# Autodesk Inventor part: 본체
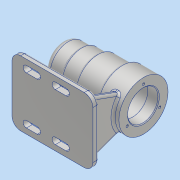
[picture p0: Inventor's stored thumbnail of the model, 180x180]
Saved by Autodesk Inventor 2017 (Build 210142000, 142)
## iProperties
Part Number: 본체
Material: 알루미늄 6061
Document SubType Name: Modeling
Designer: MRC
Density: 2.7 g/cm^3
Appearance: 알루미늄 - 평지
Author: MRC
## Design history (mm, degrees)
sketch "스케치2"
  geometry: L1 (56, 0)-(56, 34); L2 (56, 34)-(24, 34); L3 (24, 34)-(24, 30); L4 (24, 30)-(-10, 30); L5 (-10, 30)-(-10, 27); L6 (-10, 27)-(-32, 27); L7 (-32, 27)-(-32, 25); L8 (-32, 25)-(-56, 25); L9 (-56, 25)-(-56, 0); L10 (-56, 0)-(56, 0); 2 further points
  constraints: 20 end point, 8 perpendicular, 2 midpoint, 1 coincident, 1 horizontal, 1 vertical
  dimensions: "d0" = 68 diameter of L2 L10; "d1" = 60 diameter of L4 L10; "d2" = 54 diameter of L6 L10; "d3" = 50 diameter of L8 L10; "d4" = 24 distance of L7.end L8.end; "d5" = 46 distance from line of L5.end L9; "d6" = 80 distance from line of L3.end L9; "d7" = 112 distance between parallel lines of L1 L9
revolve "회전1" sketch "스케치2" stored, may be unused: angle "d8" = 90 deg
sketch "스케치3"
  geometry: L1 (56, -34)-(56, 34) reference; L2 (56, 21)-(41, 21); L3 (41, 21)-(41, 24); L4 (41, 24)-(-13, 24); L5 (-13, 24)-(-13, 21); L6 (-13, 21)-(-25, 21); L7 (-25, 21)-(-25, 17.5); L8 (-25, 17.5)-(-43, 17.5); L9 (-43, 17.5)-(-43, 16); L10 (-43, 16)-(-47, 16); L11 (-47, 16)-(-47, 10.5); L12 (-47, 10.5)-(-50, 10.5); L13 (-50, 10.5)-(-50, 0); L14 (-50, 0)-(56, 0); 1 further point
  constraints: 26 end point, 11 perpendicular, 1 horizontal, 1 midpoint, 1 point on line
  dimensions: "d9" = 21 diameter of L12 L14; "d10" = 15 distance of L2.start L2.end; "d11" = 54 distance of L3.end L4.end; "d12" = 12 distance of L5.end L6.end; "d13" = 18 distance of L7.end L8.end; "d14" = 3 distance of L11.end L12.end; "d15" = 4 distance of L9.end L10.end; "d16" = 42 diameter of L2 L14; "d17" = 48 diameter of L4 L14; "d18" = 32 diameter of L10 L14; "d19" = 35 diameter of L8 L14; "d20" = 42 diameter of L6 L14
revolve "회전2" sketch "스케치3" stored, may be unused: angle "d21" = 90 deg
fillet "모깎기1" dims "d22" = 3, "d23" = 0.3
chamfer "모따기1" distance "d24" = 1; stored, may be unused: second distance "d25" = 2, angle "d26" = 45 deg
sketch "스케치5"
  geometry: L1 (-56, -62)-(56, -62); L2 (56, -62)-(56, -70); L3 (56, -70)-(-56, -70); L4 (-56, -70)-(-56, -62); 2 further points
  constraints: 8 end point, 2 parallel, 1 horizontal, 1 midpoint, 1 perpendicular, 1 vertical alignment
  dimensions: "d27" = 8 distance of L1.end L2.end; "d28" = 70 distance from line of L3 point (0, 0); "d29" = 112 distance of L2.end L3.end
extrude "돌출1" join sketch "스케치5" stored distance "d30" = 90; taper "d31" = 0 deg
sketch "스케치6"
  geometry: L1 (0, 90)-(0, 0) reference; L2 (0, 90)-(112, 90) reference; L3 (20, 78)-(35, 78); L4 (20, 82.5)-(35, 82.5); L5 (35, 73.5)-(20, 73.5); L6 (60, 78)-(75, 78); L7 (60, 73.5)-(75, 73.5); L8 (75, 82.5)-(60, 82.5); A1 r 4.5 centre (20, 78) between (20, 82.5) and (20, 73.5); A2 r 4.5 centre (35, 78) between (35, 73.5) and (35, 82.5); A3 r 4.5 centre (60, 78) between (60, 82.5) and (60, 73.5); A4 r 4.5 centre (75, 78) between (75, 73.5) and (75, 82.5); 3 further points
  constraints: 16 end point, 8 point on circle, 8 tangent, 4 centre point, 3 parallel, 2 midpoint, 2 point on line
  dimensions: "d32" = 15 distance of L4.start L4.end; "d33" = 15 distance of L8.start L8.end; "d34" = 20 distance from line of L3.start L1; "d35" = 25 distance of L6.start L3.end; "d36" = 4.5 radius of A2; "d37" = 4.5 radius of A4; "d38" = 33 vertical distance of point (27.5, 78) point (56, 45)
extrude "돌출2" cut sketch "스케치6" stored distance "d39" = 90; taper "d40" = 0 deg
fillet "모깎기2" dims "d41" = 12
fillet "모깎기3" dims "d42" = 3, "d43" = 8
sketch "스케치7"
  geometry: L1 (-34, 0)-(0, 0); L2 (13, 22.517)-(0, 0); C1 r 22 at (0, 0) reference; 1 further point
  constraints: 4 end point, 1 horizontal, 1 horizontal alignment, 1 other
  dimensions: "d45" = 120 deg angle of L1 L2; "d46" = 26 distance of point (0, 0) L2.start
hole "구멍1" sketch "스케치7" at (13, 22.517) diameter "d47" = 3.242; stored, may be unused: countersink angle "d51" = 90 deg, drill point angle "d53" = 118 deg; dims "d48" = 8, "d49" = 4, "d50" = 2, "d52" = 11
node "작업 평면1"
sketch "스케치8"
  geometry: L1 (37, -62)-(23.409, -24.658); L2 (33, -62)-(42, -62) reference; L3 (45, -70)-(45, -65) reference; L4 (-37.5, -62)-(-28.5, -62) reference; L5 (-37.5, -62)-(-28.5, -62) reference; L6 (-37, -62)-(-23.409, -24.658); L7 (-45, -65)-(-45, -70) reference; L8 (28.5, -62)-(37.5, -62) reference; L9 (-37, -62)-(37, -62); A1 r 34 centre (0, 0) between (-23.409, -24.658) and (23.409, -24.658) reference; 1 further point
  constraints: 6 end point, 2 point on circle, 2 point on line, 1 collinear
  dimensions: "d58" = 110 deg angle of L1 L2; "d59" = 8 distance from line of L1.start L3; "d61" = 8 distance from line of L7 L6.start; "d62" = 110 deg angle of L6 L4
extrude "돌출3" join sketch "스케치8" distance "d63" = 8; taper "d64" = 0 deg
sketch "스케치9"
  geometry: L1 (-24.293, -44.434)-(-29, -62); L2 (-21, -62)-(-36, -62) reference; L3 (48, -62)-(48, -24.658) reference; 1 further point
  constraints: 2 end point, 1 point on line
  dimensions: "d65" = 105 deg angle of L1 L2; "d66" = 77 distance from line of L1.end L3
feature "리브1" sketch "스케치9" dims "d67" = 8, "d68" = 8, "d69" = 0, "d70" = 0, "d71" = 1, "d72" = 1
fillet "모깎기4" dims "d73" = 3
fillet "모깎기5" dims "d74" = 3
fillet "모깎기6" dims "d75" = 3
sketch "스케치10"
  geometry: L1 (-12, -9)-(-12, -75) reference; 2 further points
  constraints: 1 horizontal alignment, 1 other
  dimensions: "d76" = 12 distance from line of L1 point (0, -42)
feature "엠보싱1" sketch "스케치10" dims "d0" = 68, "d1" = 60, "d2" = 54, "d3" = 50, "d4" = 24, "d5" = 46, "d6" = 80, "d7" = 112, "d9" = 21, "d10" = 15, "d11" = 54, "d12" = 12, "d13" = 18, "d14" = 3, "d15" = 4, "d16" = 42, "d17" = 48, "d18" = 32, "d19" = 35, "d20" = 42, "d77" = 0.5, "d78" = 0
node "솔리드1"
mirror "미러1"
pattern_circular "원형 패턴1" dims angle "d55" = 360 deg
other parameters: "d57" = -8
